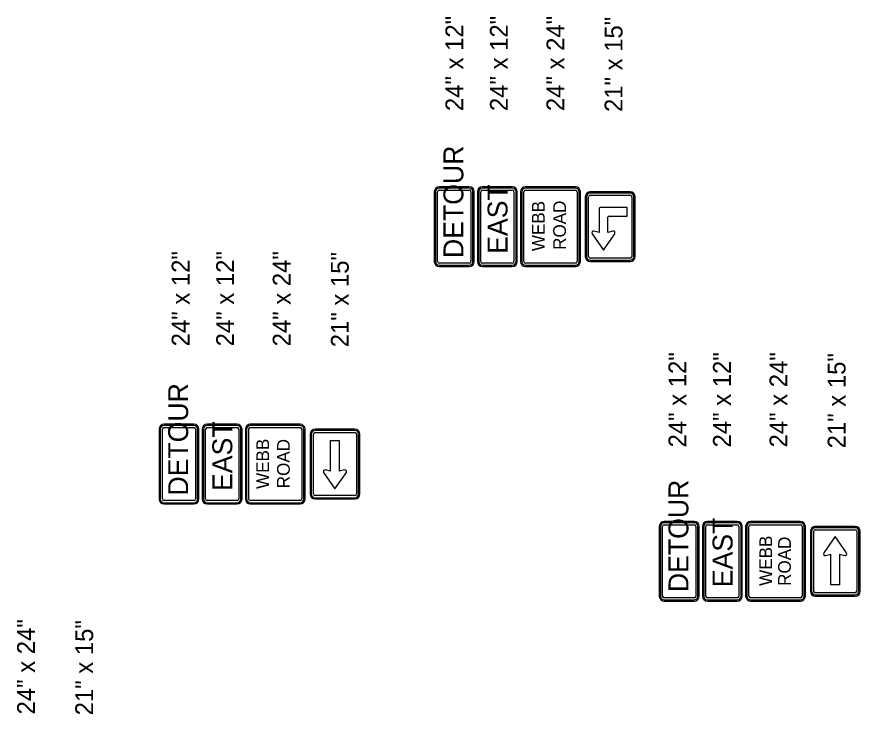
# Model space of a CAD drawing. Extents: x 1123038 to 1172987, y 554419 to 623636.
# Drawn here: x 1148039 to 1153861, y 572943 to 577757 of the extents above; entities that cross this region are included whole.
import ezdxf

# ---------------------------------------------------------------- set-up
doc = ezdxf.new("R2010")
doc.units = 0
doc.layers.add('D_Text_Standard', color=7, linetype='Continuous')
doc.layers.add('Default', color=7, linetype='Continuous')

msp = doc.modelspace()

# ---------------------------------------------------------------- linework, layer by layer
at = {"layer": 'Default'}
for p, q in [((1150921.2, 576549.1), (1150921.2, 576067.9)), ((1150929.8, 576549.1), (1150929.8, 576067.9)), ((1150944.1, 576067.9), (1150944.1, 576549.1)), ((1151161.8, 576583.5), (1150955.5, 576583.5)), ((1151161.8, 576574.9), (1150955.5, 576574.9)), ((1150955.5, 576560.6), (1151161.8, 576560.6)), ((1151173.2, 576549.1), (1151173.2, 576067.9)), ((1151187.6, 576067.9), (1151187.6, 576549.1)), ((1151196.2, 576067.9), (1151196.2, 576549.1)), ((1151219.1, 576549.1), (1151219.1, 576067.9)), ((1151227.7, 576549.1), (1151227.7, 576067.9)), ((1151242, 576067.9), (1151242, 576549.1)), ((1151459.7, 576583.5), (1151253.5, 576583.5)), ((1151459.7, 576574.9), (1151253.5, 576574.9)), ((1151253.5, 576560.6), (1151459.7, 576560.6)), ((1151471.2, 576549.1), (1151471.2, 576067.9)), ((1151485.5, 576067.9), (1151485.5, 576549.1)), ((1151494.1, 576067.9), (1151494.1, 576549.1)), ((1151517, 576549.1), (1151517, 576067.9)), ((1151525.6, 576549.1), (1151525.6, 576067.9)), ((1151539.9, 576067.9), (1151539.9, 576549.1)), ((1151895.1, 576583.5), (1151551.4, 576583.5)), ((1151895.1, 576574.9), (1151551.4, 576574.9)), ((1151551.4, 576560.6), (1151895.1, 576560.6)), ((1151906.6, 576549.1), (1151906.6, 576067.9)), ((1151920.9, 576067.9), (1151920.9, 576549.1)), ((1151929.5, 576067.9), (1151929.5, 576549.1)), ((1152273.2, 576549.1), (1151998.2, 576549.1)), ((1152273.2, 576540.5), (1151998.2, 576540.5)), ((1151963.9, 576514.7), (1151963.9, 576102.3)), ((1151972.5, 576514.7), (1151972.5, 576102.3)), ((1151986.8, 576102.3), (1151986.8, 576514.7)), ((1151998.2, 576526.2), (1152273.2, 576526.2)), ((1152284.7, 576514.7), (1152284.7, 576102.3)), ((1152299, 576102.3), (1152299, 576514.7)), ((1152307.6, 576102.3), (1152307.6, 576514.7)), ((1152058.4, 576428.8), (1152058.4, 576268.4)), ((1152251.8, 576441.7), (1152071.3, 576441.7)), ((1152251.8, 576381.6), (1152251.8, 576441.7)), ((1152118.5, 576268.4), (1152118.5, 576373)), ((1152127.1, 576381.6), (1152251.8, 576381.6)), ((1152010, 576259.4), (1152088.5, 576145.2)), ((1152058.4, 576268.4), (1152022.3, 576276.7)), ((1152088.5, 576145.2), (1152166.9, 576259.4)), ((1152154.7, 576276.7), (1152118.5, 576268.4)), ((1152273.2, 576090.8), (1151998.2, 576090.8)), ((1151998.2, 576076.5), (1152273.2, 576076.5)), ((1151998.2, 576067.9), (1152273.2, 576067.9)), ((1151161.8, 576056.4), (1150955.5, 576056.4)), ((1150955.5, 576042.1), (1151161.8, 576042.1)), ((1150955.5, 576033.5), (1151161.8, 576033.5)), ((1151459.7, 576056.4), (1151253.5, 576056.4)), ((1151253.5, 576042.1), (1151459.7, 576042.1)), ((1151253.5, 576033.5), (1151459.7, 576033.5)), ((1151895.1, 576056.4), (1151551.4, 576056.4)), ((1151551.4, 576042.1), (1151895.1, 576042.1)), ((1151551.4, 576033.5), (1151895.1, 576033.5)), ((1149020.7, 574909.7), (1149020.7, 574428.5)), ((1149029.3, 574909.7), (1149029.3, 574428.5)), ((1149043.6, 574428.5), (1149043.6, 574909.7)), ((1149261.4, 574944.1), (1149055.1, 574944.1)), ((1149261.4, 574935.5), (1149055.1, 574935.5)), ((1149055.1, 574921.2), (1149261.4, 574921.2)), ((1149272.8, 574909.7), (1149272.8, 574428.5)), ((1149287.1, 574428.5), (1149287.1, 574909.7)), ((1149295.7, 574428.5), (1149295.7, 574909.7)), ((1149318.6, 574909.7), (1149318.6, 574428.5)), ((1149327.2, 574909.7), (1149327.2, 574428.5)), ((1149341.6, 574428.5), (1149341.6, 574909.7)), ((1149559.3, 574944.1), (1149353, 574944.1)), ((1149559.3, 574935.5), (1149353, 574935.5)), ((1149353, 574921.2), (1149559.3, 574921.2)), ((1149570.7, 574909.7), (1149570.7, 574428.5)), ((1149585.1, 574428.5), (1149585.1, 574909.7)), ((1149593.6, 574428.5), (1149593.6, 574909.7)), ((1149616.6, 574909.7), (1149616.6, 574428.5)), ((1149625.2, 574909.7), (1149625.2, 574428.5)), ((1149639.5, 574428.5), (1149639.5, 574909.7)), ((1149994.7, 574944.1), (1149650.9, 574944.1)), ((1149994.7, 574935.5), (1149650.9, 574935.5)), ((1149650.9, 574921.2), (1149994.7, 574921.2)), ((1150006.1, 574909.7), (1150006.1, 574428.5)), ((1150020.5, 574428.5), (1150020.5, 574909.7)), ((1150029.1, 574428.5), (1150029.1, 574909.7)), ((1150372.8, 574909.7), (1150097.8, 574909.7)), ((1150372.8, 574901.1), (1150097.8, 574901.1)), ((1150063.4, 574875.3), (1150063.4, 574462.8)), ((1150072, 574875.3), (1150072, 574462.8)), ((1150086.4, 574462.8), (1150086.4, 574875.3)), ((1150097.8, 574886.8), (1150372.8, 574886.8)), ((1150384.3, 574875.3), (1150384.3, 574462.8)), ((1150398.6, 574462.8), (1150398.6, 574875.3)), ((1150407.2, 574462.8), (1150407.2, 574875.3)), ((1150205.2, 574832.4), (1150265.4, 574832.4)), ((1150205.2, 574620.4), (1150205.2, 574832.4)), ((1150265.4, 574832.4), (1150265.4, 574620.4)), ((1150156.9, 574611.4), (1150235.3, 574497.2)), ((1150205.2, 574620.4), (1150169.1, 574628.7)), ((1150235.3, 574497.2), (1150313.8, 574611.4)), ((1150301.5, 574628.7), (1150265.4, 574620.4)), ((1150372.8, 574451.4), (1150097.8, 574451.4)), ((1150097.8, 574437.1), (1150372.8, 574437.1)), ((1149261.4, 574417), (1149055.1, 574417)), ((1149055.1, 574402.7), (1149261.4, 574402.7)), ((1149055.1, 574394.1), (1149261.4, 574394.1)), ((1149559.3, 574417), (1149353, 574417)), ((1149353, 574402.7), (1149559.3, 574402.7)), ((1149353, 574394.1), (1149559.3, 574394.1)), ((1149994.7, 574417), (1149650.9, 574417)), ((1149650.9, 574402.7), (1149994.7, 574402.7)), ((1149650.9, 574394.1), (1149994.7, 574394.1)), ((1150097.8, 574428.5), (1150372.8, 574428.5)), ((1152715.5, 574273), (1152509.2, 574273)), ((1152715.5, 574264.4), (1152509.2, 574264.4)), ((1153013.4, 574273), (1152807.1, 574273)), ((1153013.4, 574264.4), (1152807.1, 574264.4)), ((1153448.8, 574273), (1153105.1, 574273)), ((1153448.8, 574264.4), (1153105.1, 574264.4)), ((1152474.8, 574238.7), (1152474.8, 573757.4)), ((1152483.4, 574238.7), (1152483.4, 573757.4)), ((1152497.8, 573757.4), (1152497.8, 574238.7)), ((1152509.2, 574250.1), (1152715.5, 574250.1)), ((1152726.9, 574238.7), (1152726.9, 573757.4)), ((1152741.2, 573757.4), (1152741.2, 574238.7)), ((1152749.8, 573757.4), (1152749.8, 574238.7)), ((1152772.8, 574238.7), (1152772.8, 573757.4)), ((1152781.4, 574238.7), (1152781.4, 573757.4)), ((1152795.7, 573757.4), (1152795.7, 574238.7)), ((1152807.1, 574250.1), (1153013.4, 574250.1)), ((1153024.8, 574238.7), (1153024.8, 573757.4)), ((1153039.2, 573757.4), (1153039.2, 574238.7)), ((1153047.8, 573757.4), (1153047.8, 574238.7)), ((1153070.7, 574238.7), (1153070.7, 573757.4)), ((1153079.3, 574238.7), (1153079.3, 573757.4)), ((1153093.6, 573757.4), (1153093.6, 574238.7)), ((1153105.1, 574250.1), (1153448.8, 574250.1)), ((1153460.3, 574238.7), (1153460.3, 573757.4)), ((1153474.6, 573757.4), (1153474.6, 574238.7)), ((1153483.2, 573757.4), (1153483.2, 574238.7)), ((1153517.5, 574204.3), (1153517.5, 573791.8)), ((1153526.1, 574204.3), (1153526.1, 573791.8)), ((1153540.5, 573791.8), (1153540.5, 574204.3)), ((1153826.9, 574238.7), (1153551.9, 574238.7)), ((1153826.9, 574230.1), (1153551.9, 574230.1)), ((1153551.9, 574215.8), (1153826.9, 574215.8)), ((1153838.4, 574204.3), (1153838.4, 573791.8)), ((1153852.7, 573791.8), (1153852.7, 574204.3)), ((1153861.3, 573791.8), (1153861.3, 574204.3)), ((1153689.4, 574169.9), (1153611, 574055.7)), ((1153767.9, 574055.7), (1153689.4, 574169.9)), ((1153623.2, 574038.4), (1153659.3, 574046.7)), ((1153659.3, 573834.8), (1153659.3, 574046.7)), ((1153719.5, 574046.7), (1153755.6, 574038.4)), ((1153719.5, 574046.7), (1153719.5, 573834.8)), ((1153719.5, 573834.8), (1153659.3, 573834.8)), ((1152715.5, 573746), (1152509.2, 573746)), ((1153013.4, 573746), (1152807.1, 573746)), ((1153448.8, 573746), (1153105.1, 573746)), ((1153826.9, 573780.3), (1153551.9, 573780.3)), ((1153551.9, 573766), (1153826.9, 573766)), ((1153551.9, 573757.4), (1153826.9, 573757.4)), ((1152509.2, 573731.6), (1152715.5, 573731.6)), ((1152509.2, 573723), (1152715.5, 573723)), ((1152807.1, 573731.6), (1153013.4, 573731.6)), ((1152807.1, 573723), (1153013.4, 573723)), ((1153105.1, 573731.6), (1153448.8, 573731.6)), ((1153105.1, 573723), (1153448.8, 573723))]:
    msp.add_line(p, q, dxfattribs=at)
for centre, radius, start, end in [((1150955.5, 576549.1), 34.4, 90, 180), ((1150955.5, 576549.1), 25.8, 90, 180), ((1150955.5, 576549.1), 11.5, 90, 180), ((1151161.8, 576549.1), 34.4, 0, 90), ((1151161.8, 576549.1), 25.8, 0, 90), ((1151161.8, 576549.1), 11.5, 0, 90), ((1151253.5, 576549.1), 34.4, 90, 180), ((1151253.5, 576549.1), 25.8, 90, 180), ((1151253.5, 576549.1), 11.5, 90, 180), ((1151459.7, 576549.1), 34.4, 0, 90), ((1151459.7, 576549.1), 25.8, 0, 90), ((1151459.7, 576549.1), 11.5, 0, 90), ((1151551.4, 576549.1), 34.4, 90, 180), ((1151551.4, 576549.1), 25.8, 90, 180), ((1151551.4, 576549.1), 11.5, 90, 180), ((1151895.1, 576549.1), 34.4, 0, 90), ((1151895.1, 576549.1), 25.8, 0, 90), ((1151895.1, 576549.1), 11.5, 0, 90), ((1151998.2, 576514.7), 34.4, 90, 180), ((1151998.2, 576514.7), 25.8, 90, 180), ((1152273.2, 576514.7), 34.4, 0, 90), ((1152273.2, 576514.7), 25.8, 0, 90), ((1151998.2, 576514.7), 11.5, 90, 180), ((1152273.2, 576514.7), 11.5, 0, 90), ((1152071.3, 576428.8), 12.9, 90, 180), ((1152127.1, 576373), 8.59, 90, 180), ((1152019.7, 576265.5), 11.5, 77.0497, 212.2757), ((1152157.2, 576265.5), 11.5, 327.7244, 102.9504), ((1150955.5, 576067.9), 34.4, 180, 270), ((1150955.5, 576067.9), 25.8, 180, 270), ((1150955.5, 576067.9), 11.5, 180, 270), ((1151161.8, 576067.9), 34.4, 270, 0), ((1151161.8, 576067.9), 25.8, 270, 0), ((1151161.8, 576067.9), 11.5, 270, 0), ((1151253.5, 576067.9), 34.4, 180, 270), ((1151253.5, 576067.9), 25.8, 180, 270), ((1151253.5, 576067.9), 11.5, 180, 270), ((1151459.7, 576067.9), 34.4, 270, 0), ((1151459.7, 576067.9), 25.8, 270, 0), ((1151459.7, 576067.9), 11.5, 270, 0), ((1151551.4, 576067.9), 34.4, 180, 270), ((1151551.4, 576067.9), 25.8, 180, 270), ((1151551.4, 576067.9), 11.5, 180, 270), ((1151895.1, 576067.9), 34.4, 270, 0), ((1151895.1, 576067.9), 25.8, 270, 0), ((1151895.1, 576067.9), 11.5, 270, 0), ((1151998.2, 576102.3), 34.4, 180, 270), ((1151998.2, 576102.3), 25.8, 180, 270), ((1151998.2, 576102.3), 11.5, 180, 270), ((1152273.2, 576102.3), 34.4, 270, 0), ((1152273.2, 576102.3), 25.8, 270, 0), ((1152273.2, 576102.3), 11.5, 270, 0), ((1149055.1, 574909.7), 34.4, 90, 180), ((1149055.1, 574909.7), 25.8, 90, 180), ((1149055.1, 574909.7), 11.5, 90, 180), ((1149261.4, 574909.7), 34.4, 0, 90), ((1149261.4, 574909.7), 25.8, 0, 90), ((1149261.4, 574909.7), 11.5, 0, 90), ((1149353, 574909.7), 34.4, 90, 180), ((1149353, 574909.7), 25.8, 90, 180), ((1149353, 574909.7), 11.5, 90, 180), ((1149559.3, 574909.7), 34.4, 0, 90), ((1149559.3, 574909.7), 25.8, 0, 90), ((1149559.3, 574909.7), 11.5, 0, 90), ((1149650.9, 574909.7), 34.4, 90, 180), ((1149650.9, 574909.7), 25.8, 90, 180), ((1149650.9, 574909.7), 11.5, 90, 180), ((1149994.7, 574909.7), 34.4, 0, 90), ((1149994.7, 574909.7), 25.8, 0, 90), ((1149994.7, 574909.7), 11.5, 0, 90), ((1150097.8, 574875.3), 34.4, 90, 180), ((1150097.8, 574875.3), 25.8, 90, 180), ((1150372.8, 574875.3), 34.4, 0, 90), ((1150372.8, 574875.3), 25.8, 0, 90), ((1150097.8, 574875.3), 11.5, 90, 180), ((1150372.8, 574875.3), 11.5, 0, 90), ((1150166.6, 574617.5), 11.5, 77.0497, 212.2757), ((1150304.1, 574617.5), 11.5, 327.7244, 102.9504), ((1150097.8, 574462.8), 34.4, 180, 270), ((1150097.8, 574462.8), 25.8, 180, 270), ((1150097.8, 574462.8), 11.5, 180, 270), ((1150372.8, 574462.8), 34.4, 270, 0), ((1150372.8, 574462.8), 25.8, 270, 0), ((1150372.8, 574462.8), 11.5, 270, 0), ((1149055.1, 574428.5), 34.4, 180, 270), ((1149055.1, 574428.5), 25.8, 180, 270), ((1149055.1, 574428.5), 11.5, 180, 270), ((1149261.4, 574428.5), 34.4, 270, 0), ((1149261.4, 574428.5), 25.8, 270, 0), ((1149261.4, 574428.5), 11.5, 270, 0), ((1149353, 574428.5), 34.4, 180, 270), ((1149353, 574428.5), 25.8, 180, 270), ((1149353, 574428.5), 11.5, 180, 270), ((1149559.3, 574428.5), 34.4, 270, 0), ((1149559.3, 574428.5), 25.8, 270, 0), ((1149559.3, 574428.5), 11.5, 270, 0), ((1149650.9, 574428.5), 34.4, 180, 270), ((1149650.9, 574428.5), 25.8, 180, 270), ((1149650.9, 574428.5), 11.5, 180, 270), ((1149994.7, 574428.5), 34.4, 270, 0), ((1149994.7, 574428.5), 25.8, 270, 0), ((1149994.7, 574428.5), 11.5, 270, 0), ((1152509.2, 574238.7), 34.4, 90, 180), ((1152509.2, 574238.7), 25.8, 90, 180), ((1152715.5, 574238.7), 34.4, 0, 90), ((1152715.5, 574238.7), 25.8, 0, 90), ((1152807.1, 574238.7), 34.4, 90, 180), ((1152807.1, 574238.7), 25.8, 90, 180), ((1153013.4, 574238.7), 34.4, 0, 90), ((1153013.4, 574238.7), 25.8, 0, 90), ((1153105.1, 574238.7), 34.4, 90, 180), ((1153105.1, 574238.7), 25.8, 90, 180), ((1153448.8, 574238.7), 34.4, 0, 90), ((1153448.8, 574238.7), 25.8, 0, 90), ((1152509.2, 574238.7), 11.5, 90, 180), ((1152715.5, 574238.7), 11.5, 0, 90), ((1152807.1, 574238.7), 11.5, 90, 180), ((1153013.4, 574238.7), 11.5, 0, 90), ((1153105.1, 574238.7), 11.5, 90, 180), ((1153448.8, 574238.7), 11.5, 0, 90), ((1153551.9, 574204.3), 34.4, 90, 180), ((1153551.9, 574204.3), 25.8, 90, 180), ((1153551.9, 574204.3), 11.5, 90, 180), ((1153826.9, 574204.3), 34.4, 0, 90), ((1153826.9, 574204.3), 25.8, 0, 90), ((1153826.9, 574204.3), 11.5, 0, 90), ((1153620.7, 574049.6), 11.5, 147.7244, 282.9503), ((1153758.2, 574049.6), 11.5, 257.0497, 32.2757), ((1153551.9, 573791.8), 34.4, 180, 270), ((1153551.9, 573791.8), 25.8, 180, 270), ((1153551.9, 573791.8), 11.5, 180, 270), ((1153826.9, 573791.8), 34.4, 270, 0), ((1153826.9, 573791.8), 25.8, 270, 0), ((1153826.9, 573791.8), 11.5, 270, 0), ((1152509.2, 573757.4), 34.4, 180, 270), ((1152509.2, 573757.4), 25.8, 180, 270), ((1152509.2, 573757.4), 11.5, 180, 270), ((1152715.5, 573757.4), 34.4, 270, 0), ((1152715.5, 573757.4), 25.8, 270, 0), ((1152715.5, 573757.4), 11.5, 270, 0), ((1152807.1, 573757.4), 34.4, 180, 270), ((1152807.1, 573757.4), 25.8, 180, 270), ((1152807.1, 573757.4), 11.5, 180, 270), ((1153013.4, 573757.4), 34.4, 270, 0), ((1153013.4, 573757.4), 25.8, 270, 0), ((1153013.4, 573757.4), 11.5, 270, 0), ((1153105.1, 573757.4), 34.4, 180, 270), ((1153105.1, 573757.4), 25.8, 180, 270), ((1153105.1, 573757.4), 11.5, 180, 270), ((1153448.8, 573757.4), 34.4, 270, 0), ((1153448.8, 573757.4), 25.8, 270, 0), ((1153448.8, 573757.4), 11.5, 270, 0)]:
    msp.add_arc(centre, radius, start, end, dxfattribs=at)

# ---------------------------------------------------------------- texts
at = {"layer": 'D_Text_Standard'}
for s, p in [('24" x 12"', (1151121.5, 577106.5)), ('24" x 12"', (1151428.6, 577106.5)), ('24" x 24"', (1151819, 577106.5)), ('21" x 15"', (1152220.5, 577100.2)), ('24" x 12"', (1149231.3, 575482.1)), ('24" x 12"', (1149538.3, 575482.1)), ('24" x 24"', (1149928.8, 575482.1)), ('21" x 15"', (1150330.3, 575475.8)), ('24" x 12"', (1152661.6, 574784.1)), ('24" x 12"', (1152968.7, 574784.1)), ('24" x 24"', (1153359.1, 574784.1)), ('21" x 15"', (1153760.6, 574777.8)), ('24" x 24"', (1148164, 572940.8)), ('21" x 15"', (1148565.5, 572934.4))]:
    msp.add_text(s, height=123.19, rotation=90, dxfattribs=at).set_placement(p)
at = {"layer": 'Default'}
for s, height, p in [('DETOUR', 137.5, (1151121.8, 576091.8)), ('EAST', 137.5, (1151426.6, 576120.9)), ('WEBB', 88, (1151683.4, 576139.5)), ('ROAD', 88, (1151830.1, 576148.2)), ('DETOUR', 137.5, (1149221.4, 574451.7)), ('EAST', 137.5, (1149526.2, 574483.5)), ('WEBB', 88, (1149780.5, 574497.5)), ('ROAD', 88, (1149923.4, 574502.3)), ('DETOUR', 137.5, (1152675.5, 573785.1)), ('EAST', 137.5, (1152980.3, 573819.1)), ('WEBB', 88, (1153253.8, 573828.6)), ('ROAD', 88, (1153383, 573828.2))]:
    msp.add_text(s, height=height, rotation=90, dxfattribs=at).set_placement(p)

doc.saveas('drawing.dxf')
